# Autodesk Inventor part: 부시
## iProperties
Company: 한국ATC센터
Created: 2014-10
Part Number: 부시
Document SubType Name: Modeling
Designer: 한국ATC센터
Density: 7.86 g/cm^3
Material: 강, 연강
Mass: 157.788 g
Surface Area: 70.2617 cm^2
Volume: 20.0748 cm^3
Author: KYOUNG IL JANG
Revision Number: 1
